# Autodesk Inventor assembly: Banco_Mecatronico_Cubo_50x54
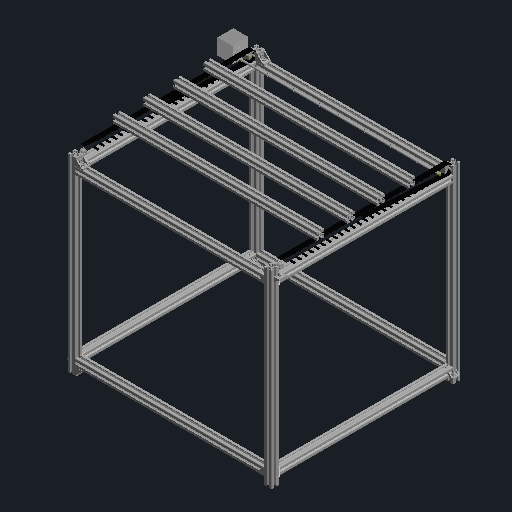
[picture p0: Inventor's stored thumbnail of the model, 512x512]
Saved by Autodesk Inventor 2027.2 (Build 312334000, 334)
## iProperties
Part Number: Banco_Mecatronico_Cubo_50x54
Document SubType Name: Ensamblaje
Designer: Usuario
Author: Usuario
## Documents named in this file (11)
- C:\Users\Usuario\Desktop\universidad\clase\TFG\DESARROLLO_TFG\Parte mecanica\Inventor\ensamblajes\Banco_Mecatronico_Cubo_50x54.iam
- C:\Users\Usuario\Desktop\universidad\clase\TFG\DESARROLLO_TFG\Parte mecanica\Inventor\piezas\Perfil_2020_L500.ipt
- C:\Users\Usuario\Desktop\universidad\clase\TFG\DESARROLLO_TFG\Parte mecanica\Inventor\piezas\Perfil_2020_L460.ipt
- C:\Users\Usuario\Desktop\universidad\clase\TFG\DESARROLLO_TFG\Parte mecanica\Inventor\piezas\Escuadra_90_Fundicion_2020.ipt
- C:\Users\Usuario\Desktop\universidad\clase\TFG\DESARROLLO_TFG\Parte mecanica\Inventor\piezas\Tornillo_M5x8_DIN912.ipt
- C:\Users\Usuario\Desktop\universidad\clase\TFG\DESARROLLO_TFG\Parte mecanica\Inventor\piezas\Cinta_Transportadora_20mm_L500.ipt
- C:\Users\Usuario\Desktop\universidad\clase\TFG\DESARROLLO_TFG\Parte mecanica\Inventor\piezas\Engranaje_Recto_1a1_m1_Z20.ipt
- C:\Users\Usuario\Desktop\universidad\clase\TFG\DESARROLLO_TFG\Parte mecanica\Inventor\piezas\Motor_NEMA17.ipt
- C:\Users\Usuario\Desktop\universidad\clase\TFG\DESARROLLO_TFG\Parte mecanica\Inventor\piezas\Eje_Distribucion_5mm_L520.ipt
- C:\Users\Usuario\Desktop\universidad\clase\TFG\DESARROLLO_TFG\Parte mecanica\Inventor\piezas\Polea_GT2_20T.ipt
- C:\Users\Usuario\Desktop\universidad\clase\TFG\DESARROLLO_TFG\Parte mecanica\Inventor\piezas\Perfil_2020_L540.ipt
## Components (73 placed, 10 different names)
1. Perfil_2020_L500:1
2. Perfil_2020_L500:2
3. Perfil_2020_L500:3
4. Perfil_2020_L500:4
5. Perfil_2020_L500:5
6. Perfil_2020_L500:6
7. Perfil_2020_L460:1
8. Perfil_2020_L460:2
9. Perfil_2020_L500:7
10. Perfil_2020_L500:8
11. Perfil_2020_L460:3
12. Perfil_2020_L460:4
13. Escuadra_90_Fundicion_2020:1
14. Tornillo_M5x8_DIN912:1
15. Tornillo_M5x8_DIN912:2
16. Escuadra_90_Fundicion_2020:2
17. Tornillo_M5x8_DIN912:3
18. Tornillo_M5x8_DIN912:4
19. Escuadra_90_Fundicion_2020:3
20. Tornillo_M5x8_DIN912:5
21. Tornillo_M5x8_DIN912:6
22. Escuadra_90_Fundicion_2020:4
23. Tornillo_M5x8_DIN912:7
24. Tornillo_M5x8_DIN912:8
25. Escuadra_90_Fundicion_2020:5
26. Tornillo_M5x8_DIN912:9
27. Tornillo_M5x8_DIN912:10
28. Escuadra_90_Fundicion_2020:6
29. Tornillo_M5x8_DIN912:11
30. Tornillo_M5x8_DIN912:12
31. Escuadra_90_Fundicion_2020:7
32. Tornillo_M5x8_DIN912:13
33. Tornillo_M5x8_DIN912:14
34. Escuadra_90_Fundicion_2020:8
35. Tornillo_M5x8_DIN912:15
36. Tornillo_M5x8_DIN912:16
37. Escuadra_90_Fundicion_2020:9
38. Tornillo_M5x8_DIN912:17
39. Tornillo_M5x8_DIN912:18
40. Escuadra_90_Fundicion_2020:10
41. Tornillo_M5x8_DIN912:19
42. Tornillo_M5x8_DIN912:20
43. Escuadra_90_Fundicion_2020:11
44. Tornillo_M5x8_DIN912:21
45. Tornillo_M5x8_DIN912:22
46. Escuadra_90_Fundicion_2020:12
47. Tornillo_M5x8_DIN912:23
48. Tornillo_M5x8_DIN912:24
49. Escuadra_90_Fundicion_2020:13
50. Tornillo_M5x8_DIN912:25
51. Tornillo_M5x8_DIN912:26
52. Escuadra_90_Fundicion_2020:14
53. Tornillo_M5x8_DIN912:27
54. Tornillo_M5x8_DIN912:28
55. Escuadra_90_Fundicion_2020:15
56. Tornillo_M5x8_DIN912:29
57. Tornillo_M5x8_DIN912:30
58. Escuadra_90_Fundicion_2020:16
59. Tornillo_M5x8_DIN912:31
60. Tornillo_M5x8_DIN912:32
61. Cinta_Transportadora_20mm_L500:1
62. Cinta_Transportadora_20mm_L500:2
63. Engranaje_Recto_1a1_m1_Z20:1
64. Engranaje_Recto_1a1_m1_Z20:2
65. Motor_NEMA17:1
66. Eje_Distribucion_5mm_L520:1
67. Engranaje_Recto_1a1_m1_Z20:3
68. Polea_GT2_20T:1
69. Polea_GT2_20T:2
70. Perfil_2020_L540:1
71. Perfil_2020_L540:2
72. Perfil_2020_L540:3
73. Perfil_2020_L540:4
